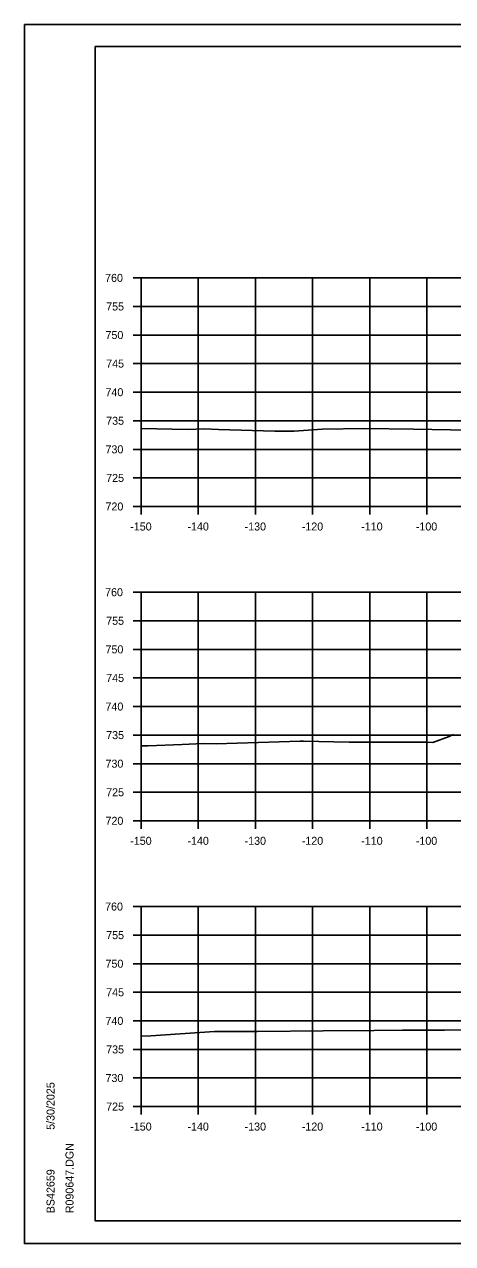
# Model space of a CAD drawing. Extents: x 1202951 to 1376887, y 378065 to 728038.
# Drawn here: x 1372926.7 to 1373001.6, y 380522.4 to 380735.8 of the extents above; entities that cross this region are included whole.
import ezdxf

# ---------------------------------------------------------------- set-up
doc = ezdxf.new("R2010")
doc.units = 0
for name, color, linetype in [('R_Axis', 7, 'Continuous'), ('R_Axis Annot', 7, 'Continuous'), ('R_Exist Surface', 7, 'Continuous'), ('R_Grid', 7, 'Continuous'), ('R_No Plot', 7, 'Continuous')]:
    doc.layers.add(name, color=color, linetype=linetype)

msp = doc.modelspace()

# ---------------------------------------------------------------- linework, layer by layer
at = {"layer": 'R_Axis'}
for p, q in [((1372945.73, 380691.4), (1372947.13, 380691.4)), ((1372947.13, 380651.4), (1372947.13, 380691.4)), ((1372945.73, 380686.4), (1372947.13, 380686.4)), ((1372945.73, 380681.4), (1372947.13, 380681.4)), ((1372945.73, 380676.4), (1372947.13, 380676.4)), ((1372945.73, 380671.4), (1372947.13, 380671.4)), ((1372945.73, 380666.4), (1372947.13, 380666.4)), ((1372945.73, 380661.4), (1372947.13, 380661.4)), ((1372945.73, 380656.4), (1372947.13, 380656.4)), ((1372945.73, 380651.4), (1372947.13, 380651.4)), ((1372947.13, 380651.4), (1373247.13, 380651.4)), ((1372947.13, 380650), (1372947.13, 380651.4)), ((1372957.13, 380650), (1372957.13, 380651.4)), ((1372967.13, 380650), (1372967.13, 380651.4)), ((1372977.13, 380650), (1372977.13, 380651.4)), ((1372987.13, 380650), (1372987.13, 380651.4)), ((1372997.13, 380650), (1372997.13, 380651.4)), ((1372945.73, 380636.4), (1372947.13, 380636.4)), ((1372947.13, 380596.4), (1372947.13, 380636.4)), ((1372945.73, 380631.4), (1372947.13, 380631.4)), ((1372945.73, 380626.4), (1372947.13, 380626.4)), ((1372945.73, 380621.4), (1372947.13, 380621.4)), ((1372945.73, 380616.4), (1372947.13, 380616.4)), ((1372945.73, 380611.4), (1372947.13, 380611.4)), ((1372945.73, 380606.4), (1372947.13, 380606.4)), ((1372945.73, 380601.4), (1372947.13, 380601.4)), ((1372945.73, 380596.4), (1372947.13, 380596.4)), ((1372947.13, 380596.4), (1373247.13, 380596.4)), ((1372947.13, 380595), (1372947.13, 380596.4)), ((1372957.13, 380595), (1372957.13, 380596.4)), ((1372967.13, 380595), (1372967.13, 380596.4)), ((1372977.13, 380595), (1372977.13, 380596.4)), ((1372987.13, 380595), (1372987.13, 380596.4)), ((1372997.13, 380595), (1372997.13, 380596.4)), ((1372945.73, 380581.4), (1372947.13, 380581.4)), ((1372947.13, 380546.4), (1372947.13, 380581.4)), ((1372945.73, 380576.4), (1372947.13, 380576.4)), ((1372945.73, 380571.4), (1372947.13, 380571.4)), ((1372945.73, 380566.4), (1372947.13, 380566.4)), ((1372945.73, 380561.4), (1372947.13, 380561.4)), ((1372945.73, 380556.4), (1372947.13, 380556.4)), ((1372945.73, 380551.4), (1372947.13, 380551.4)), ((1372945.73, 380546.4), (1372947.13, 380546.4)), ((1372947.13, 380546.4), (1373247.13, 380546.4)), ((1372947.13, 380545), (1372947.13, 380546.4)), ((1372957.13, 380545), (1372957.13, 380546.4)), ((1372967.13, 380545), (1372967.13, 380546.4)), ((1372977.13, 380545), (1372977.13, 380546.4)), ((1372987.13, 380545), (1372987.13, 380546.4)), ((1372997.13, 380545), (1372997.13, 380546.4))]:
    msp.add_line(p, q, dxfattribs=at)
at = {"layer": 'R_Exist Surface'}
for points in [[(1372947.13, 380665.02), (1372955.29, 380664.89), (1372958.18, 380664.99), (1372960.65, 380664.85), (1372970.55, 380664.6), (1372973.91, 380664.59), (1372978.83, 380664.96), (1372986.22, 380665.03), (1372994.79, 380664.92), (1373007.71, 380664.67)], [(1372947.13, 380609.5), (1372948.33, 380609.5), (1372954.32, 380609.74), (1372958, 380609.95), (1372960.25, 380609.9), (1372974.97, 380610.31), (1372975.2, 380610.31), (1372975.53, 380610.33), (1372983.56, 380610.16), (1372986.7, 380610.16), (1372997.24, 380610.17), (1372998.17, 380610.09), (1373001, 380611.13), (1373001.8, 380611.49)], [(1372947.13, 380558.71), (1372948.87, 380558.8), (1372959.96, 380559.52), (1372963.44, 380559.52), (1372964.97, 380559.52), (1372967.49, 380559.54), (1372978.99, 380559.65), (1372987.89, 380559.72), (1372992.88, 380559.76), (1373000.23, 380559.78), (1373005.9, 380559.82)]]:
    msp.add_lwpolyline(points, dxfattribs=at)
at = {"layer": 'R_Grid'}
for p, q in [((1372947.13, 380691.4), (1373247.13, 380691.4)), ((1372947.13, 380651.4), (1372947.13, 380691.4)), ((1372957.13, 380651.4), (1372957.13, 380691.4)), ((1372967.13, 380651.4), (1372967.13, 380691.4)), ((1372977.13, 380651.4), (1372977.13, 380691.4)), ((1372987.13, 380651.4), (1372987.13, 380691.4)), ((1372997.13, 380651.4), (1372997.13, 380691.4)), ((1372947.13, 380686.4), (1373247.13, 380686.4)), ((1372947.13, 380681.4), (1373247.13, 380681.4)), ((1372947.13, 380676.4), (1373247.13, 380676.4)), ((1372947.13, 380671.4), (1373247.13, 380671.4)), ((1372947.13, 380666.4), (1373247.13, 380666.4)), ((1372947.13, 380661.4), (1373247.13, 380661.4)), ((1372947.13, 380656.4), (1373247.13, 380656.4)), ((1372947.13, 380651.4), (1373247.13, 380651.4)), ((1372947.13, 380636.4), (1373247.13, 380636.4)), ((1372947.13, 380596.4), (1372947.13, 380636.4)), ((1372957.13, 380596.4), (1372957.13, 380636.4)), ((1372967.13, 380596.4), (1372967.13, 380636.4)), ((1372977.13, 380596.4), (1372977.13, 380636.4)), ((1372987.13, 380596.4), (1372987.13, 380636.4)), ((1372997.13, 380596.4), (1372997.13, 380636.4)), ((1372947.13, 380631.4), (1373247.13, 380631.4)), ((1372947.13, 380626.4), (1373247.13, 380626.4)), ((1372947.13, 380621.4), (1373247.13, 380621.4)), ((1372947.13, 380616.4), (1373247.13, 380616.4)), ((1372947.13, 380611.4), (1373247.13, 380611.4)), ((1372947.13, 380606.4), (1373247.13, 380606.4)), ((1372947.13, 380601.4), (1373247.13, 380601.4)), ((1372947.13, 380596.4), (1373247.13, 380596.4)), ((1372947.13, 380581.4), (1373247.13, 380581.4)), ((1372947.13, 380546.4), (1372947.13, 380581.4)), ((1372957.13, 380546.4), (1372957.13, 380581.4)), ((1372967.13, 380546.4), (1372967.13, 380581.4)), ((1372977.13, 380546.4), (1372977.13, 380581.4)), ((1372987.13, 380546.4), (1372987.13, 380581.4)), ((1372997.13, 380546.4), (1372997.13, 380581.4)), ((1372947.13, 380576.4), (1373247.13, 380576.4)), ((1372947.13, 380571.4), (1373247.13, 380571.4)), ((1372947.13, 380566.4), (1373247.13, 380566.4)), ((1372947.13, 380561.4), (1373247.13, 380561.4)), ((1372947.13, 380556.4), (1373247.13, 380556.4)), ((1372947.13, 380551.4), (1373247.13, 380551.4)), ((1372947.13, 380546.4), (1373247.13, 380546.4))]:
    msp.add_line(p, q, dxfattribs=at)
at = {"layer": 'R_No Plot'}
for p, q in [((1372926.73, 380735.76), (1373260.07, 380735.76)), ((1372939.13, 380731.86), (1373255.31, 380731.86)), ((1372939.13, 380526.4), (1372939.13, 380731.86)), ((1372939.13, 380526.4), (1372939.13, 380526.4)), ((1373255.31, 380526.4), (1372939.13, 380526.4)), ((1372926.73, 380522.43), (1373260.07, 380522.43))]:
    msp.add_line(p, q, dxfattribs=at)
for points in [[(1372926.73, 380735.76), (1373260.07, 380735.76), (1373260.07, 380522.42), (1372926.73, 380522.42)], [(1373173.05, 380731.86), (1373192.67, 380731.86), (1373192.67, 380721.98), (1373208.79, 380721.98), (1373231.99, 380721.98), (1373231.99, 380697.65), (1373255.31, 380697.65), (1373255.31, 380526.4), (1372939.13, 380526.4), (1372939.13, 380731.86)]]:
    msp.add_lwpolyline(points, close=True, dxfattribs=at)

# ---------------------------------------------------------------- texts
at = {"layer": 'R_Axis Annot'}
for s, p in [('760', (1372940.84, 380690.7)), ('755', (1372941.03, 380685.7)), ('750', (1372940.91, 380680.7)), ('745', (1372941.03, 380675.7)), ('740', (1372940.91, 380670.7)), ('735', (1372941.03, 380665.7)), ('730', (1372940.91, 380660.7)), ('725', (1372941.03, 380655.7)), ('720', (1372940.91, 380650.7)), ('-150', (1372945.24, 380647.2)), ('-140', (1372955.24, 380647.2)), ('-130', (1372965.24, 380647.2)), ('-120', (1372975.24, 380647.2)), ('-110', (1372985.64, 380647.2)), ('-100', (1372995.19, 380647.2)), ('760', (1372940.84, 380635.7)), ('755', (1372941.03, 380630.7)), ('750', (1372940.91, 380625.7)), ('745', (1372941.03, 380620.7)), ('740', (1372940.91, 380615.7)), ('735', (1372941.03, 380610.7)), ('730', (1372940.91, 380605.7)), ('725', (1372941.03, 380600.7)), ('720', (1372940.91, 380595.7)), ('-150', (1372945.24, 380592.2)), ('-140', (1372955.24, 380592.2)), ('-130', (1372965.24, 380592.2)), ('-120', (1372975.24, 380592.2)), ('-110', (1372985.64, 380592.2)), ('-100', (1372995.19, 380592.2)), ('760', (1372940.84, 380580.7)), ('755', (1372941.03, 380575.7)), ('750', (1372940.91, 380570.7)), ('745', (1372941.03, 380565.7)), ('740', (1372940.91, 380560.7)), ('735', (1372941.03, 380555.7)), ('730', (1372940.91, 380550.7)), ('725', (1372941.03, 380545.7)), ('-150', (1372945.24, 380542.2)), ('-140', (1372955.24, 380542.2)), ('-130', (1372965.24, 380542.2)), ('-120', (1372975.24, 380542.2)), ('-110', (1372985.64, 380542.2)), ('-100', (1372995.19, 380542.2))]:
    msp.add_text(s, height=1.4, dxfattribs=at).set_placement(p)
at = {"layer": 'R_No Plot'}
for s, p in [('5/30/2025', (1372932, 380542.33)), ('R090647.DGN', (1372935.32, 380527.73)), ('BS42659', (1372932, 380527.73))]:
    msp.add_text(s, height=1.4, rotation=90, dxfattribs=at).set_placement(p)

doc.saveas('drawing.dxf')
